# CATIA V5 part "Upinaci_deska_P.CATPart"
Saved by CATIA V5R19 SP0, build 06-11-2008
Part number: Upinaci_deska_P
Nomenclature: FM 50_75 75_20.5_2312
Source: Unknown
Description: PART-FM 50_75 75_20.5_2312-DESC
Bounding box of the stored display mesh (mm): x -37.5 to 37.5, y -37.5 to 37.5, z 0 to 20.5
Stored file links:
  C:\Users\jsmid\Desktop\DP_Smidak_Forma LEGO\Upinaci_deska_P.CATPart
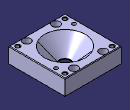
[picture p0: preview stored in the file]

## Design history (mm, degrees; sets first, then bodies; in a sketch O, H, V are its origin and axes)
Body1 "FM 50_75 75_20.5_2312" (main body)
  Solid1: solid without history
